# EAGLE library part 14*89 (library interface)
Quad line receivers BUFFER,
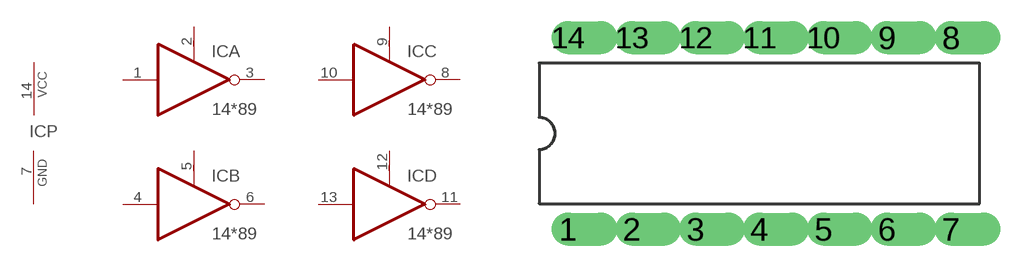
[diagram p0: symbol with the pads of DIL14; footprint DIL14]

Designator prefix IC; gates A=1489 B=1489 C=1489 D=1489 P=PWRN

## 1489N, 14C89N  [DIL14]
1  A:I  in
2  A:RC  in
3  A:O  out
4  B:I  in
5  B:RC  in
6  B:O  out
7  P:GND  pwr
8  C:O  out
9  C:RC  in
10  C:I  in
11  D:O  out
12  D:RC  in
13  D:I  in
14  P:VCC  pwr

## Footprint DIL14 (pad centres in mm)
Dual In Line 14
drill 0.8 offset: 1 -7.62,-3.81; 2 -5.08,-3.81; 3 -2.54,-3.81; 4 0,-3.81; 5 2.54,-3.81; 6 5.08,-3.81; 7 7.62,-3.81; 8 7.62,3.81; 9 5.08,3.81; 10 2.54,3.81; 11 0,3.81; 12 -2.54,3.81; 13 -5.08,3.81; 14 -7.62,3.81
